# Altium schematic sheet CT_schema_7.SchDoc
size 391 x 238 mm
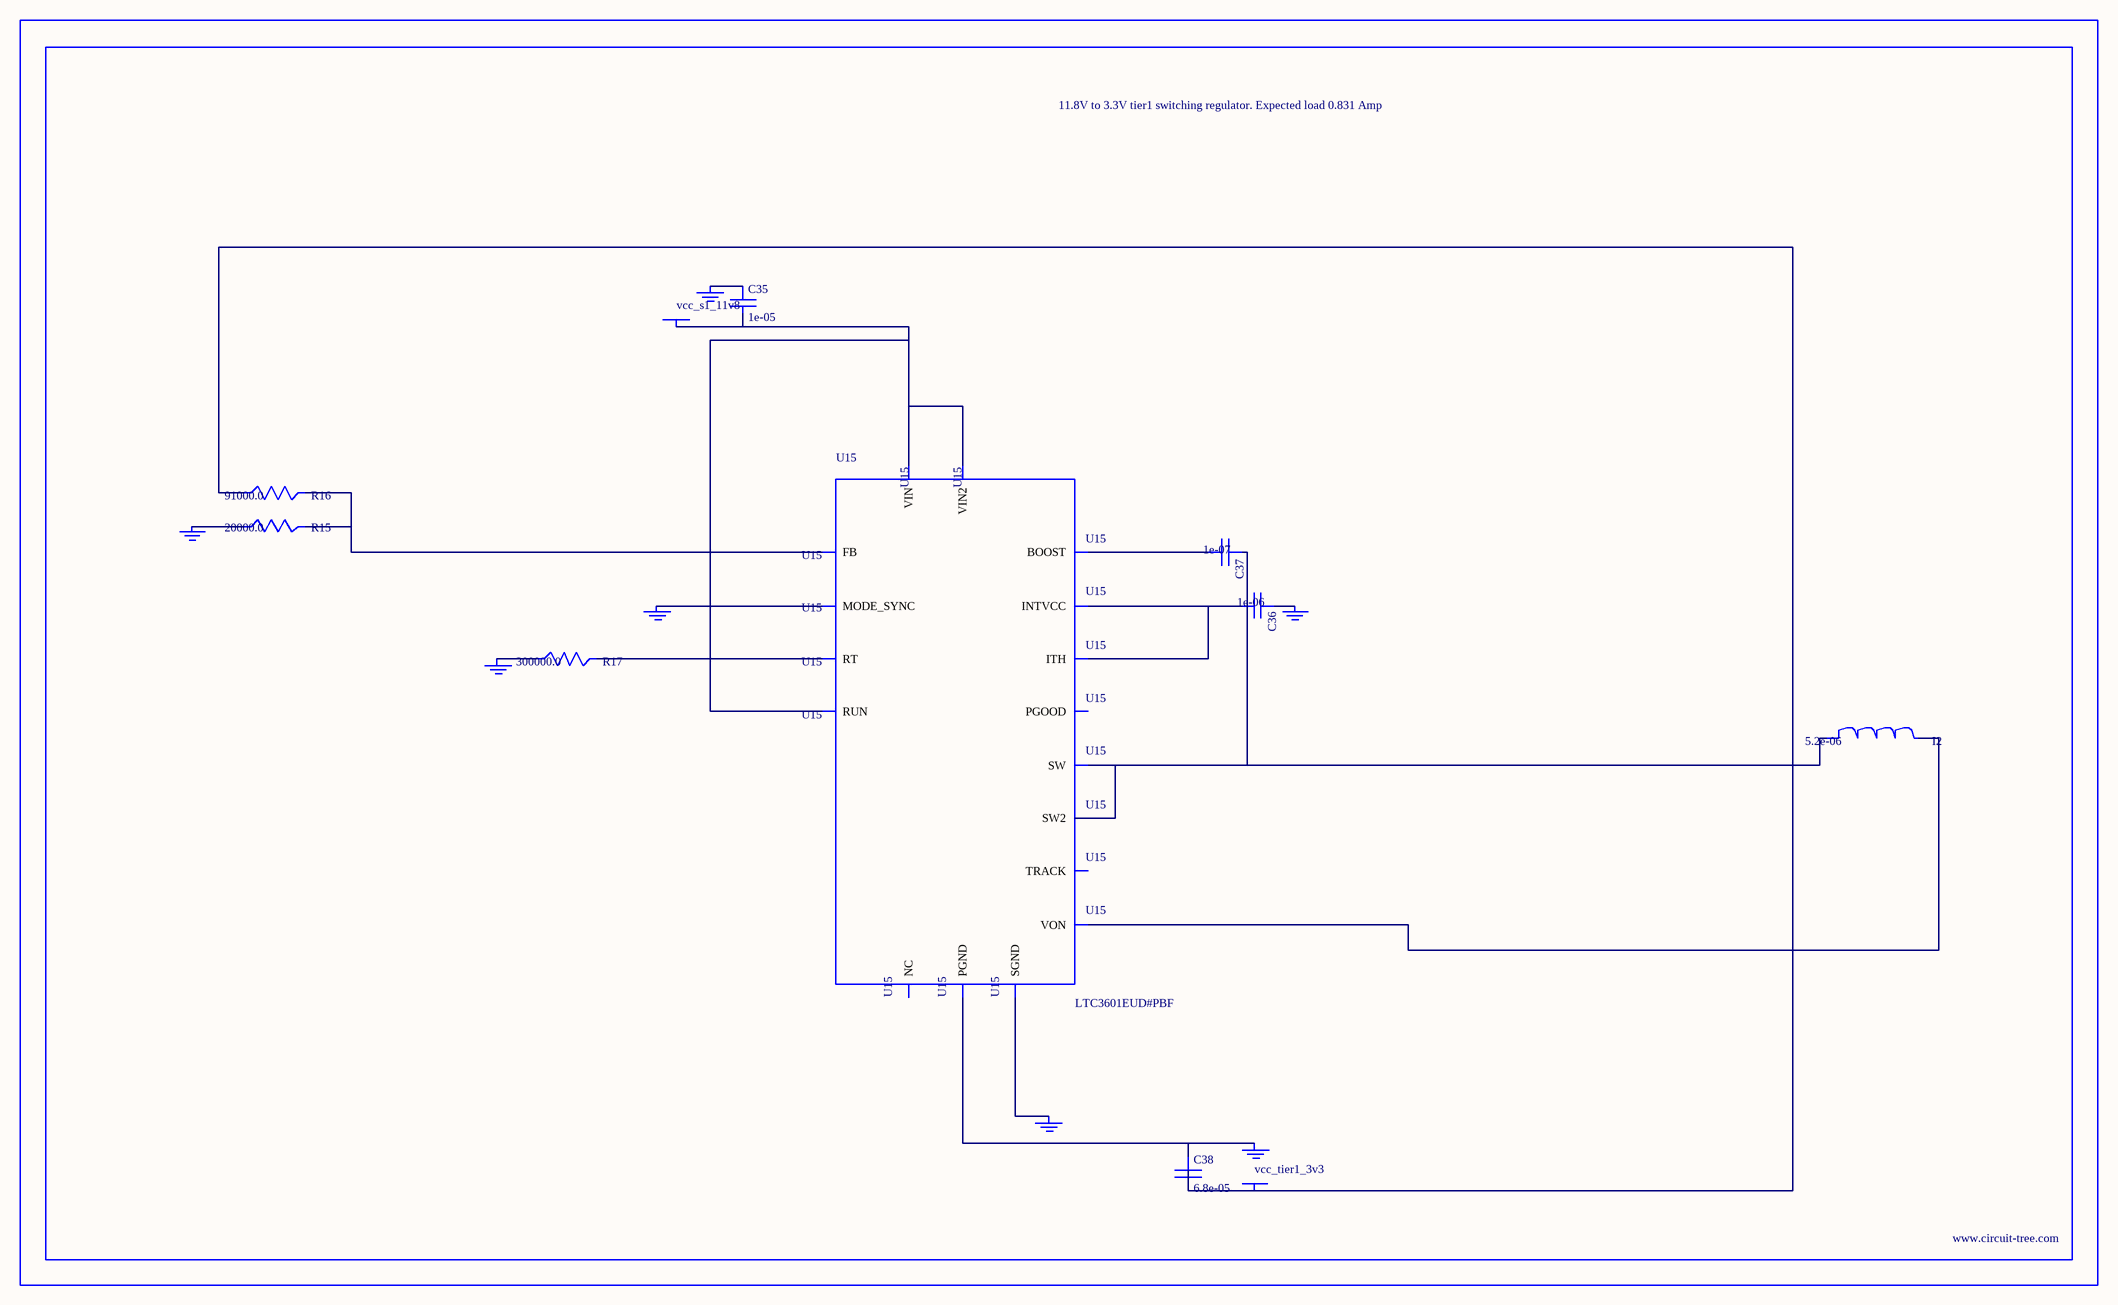
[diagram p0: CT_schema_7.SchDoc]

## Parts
BORDER6  (no value)
C35  1e-05  [C0805]
C36  1e-06  [C0603]
C37  1e-07  [C0402]
C38  6.8e-05  [2220]
GND_INSTANCE_6_0  (no value)
GND_INSTANCE_6_1  (no value)
GND_INSTANCE_6_2  (no value)
GND_INSTANCE_6_3  (no value)
GND_INSTANCE_6_4  (no value)
GND_INSTANCE_6_5  (no value)
GND_INSTANCE_6_6  (no value)
I2  5.2e-06  [DR1040]
POWER_INSTANCE_6_0  vcc_s1_11v8
POWER_INSTANCE_6_1  vcc_tier1_3v3
R15  20000.0  [R0603]
R16  91000.0  [R0603]
R17  300000.0  [R0603]
U15  LTC3601EUD#PBF  [QFN-16_EP]

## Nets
NetC35_1: C35.1 GND_INSTANCE_6_5.0(GND)
NetC35_2: C35.2 POWER_INSTANCE_6_0.0(PWR) U15.14(RUN) U15.15(VIN) U15.16(VIN2)
NetC36_1: C36.1 GND_INSTANCE_6_1.0(GND)
NetC36_2: C36.2 U15.7(INTVCC) U15.12(ITH)
NetC37_1: C37.1 I2.1 U15.3(SW) U15.4(SW2)
NetC37_2: C37.2 U15.6(BOOST)
NetC38_1: C38.1 GND_INSTANCE_6_6.0(GND) U15.17(PGND)
NetC38_2: C38.2 I2.2 POWER_INSTANCE_6_1.0(PWR) R16.1 U15.8(VON)
NetGND_INSTANCE_6_0_0: GND_INSTANCE_6_0.0(GND) U15.1(MODE_SYNC)
NetGND_INSTANCE_6_2_0: GND_INSTANCE_6_2.0(GND) U15.9(SGND)
NetGND_INSTANCE_6_3_0: GND_INSTANCE_6_3.0(GND) R17.1
NetGND_INSTANCE_6_4_0: GND_INSTANCE_6_4.0(GND) R15.1
NetR15_2: R15.2 R16.2 U15.11(FB)
NetR17_2: R17.2 U15.10(RT)

Not connected (* = marked no-connect by the designer): U15 2(PGOOD) 5(NC) 13(TRACK)

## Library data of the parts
BORDER6 = BORDER_PAGE6
C35 = C0805C106K8RACTU
C36 = C0603C105K3RACTU
C37 = C0402C104K3RACTU
C38 = C5750X5R1A686M
GND_INSTANCE_6_0-GND_INSTANCE_6_6 = GND
I2 = DR1040-5R2-R
POWER_INSTANCE_6_0 POWER_INSTANCE_6_1 = PWR
R15 = RC0603JR-0720KL
R16 = RC0603JR-0791KL
R17 = RC0603JR-07300KL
